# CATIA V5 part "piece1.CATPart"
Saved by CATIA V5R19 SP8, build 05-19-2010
Part number: piece1
Bounding box of the stored display mesh (mm): x -20 to 20, y -85.522 to 100.479, z -20 to 67.521
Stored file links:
  U:\554\piece1.CATPart
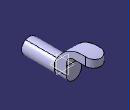
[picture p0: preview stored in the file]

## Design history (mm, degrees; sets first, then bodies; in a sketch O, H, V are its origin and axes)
Body1 (main body)
  Sketch1 on yz-plane, origin (0, 0, 0), H (0, 1, 0), V (0, 0, 1)
    point P1 (-85.5219, 0)
    line L1 (-85.5219, 0) -> (0, 0)
    line L2 (0, 0) -> (0, 20)
    line L3 (0, 20) -> (-85.5219, 20)
    line L4 (-85.5219, 20) -> (-85.5219, 0)
    point P3 (0, 20)
    length L4 = 20
    coincidence: P1 H, P3 V
    horizontal: L1 H, L3 H
    vertical: L2 V, L4 V
  Shaft1: profile Sketch1, axis Sketch1.L1, angle 360
  Sketch2 on yz-plane, origin (0, 0, 0), H (0, 1, 0), V (0, 0, 1)
    spline S1 through (0, 14.9789) (40.6517, 60.2998) (100.4787, 64.5247)
    point P1 (0, -22.9588)
    line L1 (0, -22.9588) -> (30.4581, -22.9588)
    line L2 (30.4581, -22.9588) -> (30.4581, 20.7401)
    line L3 (100.4787, 64.5247) -> (100.4787, 46.089)
    line L4 (100.4787, 46.089) -> (48.3218, 46.089)
    point P6 (100.4787, 64.5247)
    connectcurve C1
    line L5 (0, 14.9789) -> (0, -22.9588)
    point P7 (0, 14.9789)
    point P8 (0, 14.9789)
    point P9 (100.4787, 64.5247)
    coincidence: P8 V, P1 V, P9 P6, P8 P7
    horizontal: L1 H, L4 H
    vertical: L2 V, L3 V, L5 V
  Pad1: profile Sketch2, direction (1, 0, 0), length 20, mirrored extent
  Sketch3 on face of Pad1 from Sketch2.L2, origin (0, 30.4581, 0), H (-1, 0, 0), V (0, 0, 1)
    arc A1 centre (0, 0) radius 20 from (-20, 0) to (20, 0) ccw
    point P1 (20, 0)
    line L1 (20, 0) -> (51.8214, 0)
    line L2 (51.8214, 0) -> (51.8214, -50.6716)
    line L3 (51.8214, -50.6716) -> (-51.8214, -50.6716)
    line L4 (-51.8214, -50.6716) -> (-51.8214, 0)
    point P5 (-51.8214, 0)
    line L5 (-51.8214, 0) -> (-20, 0)
    point P6 (-20, 0)
    point P7 (-20, 0)
    point P8 (20, 0)
    reference projected circle E1 centre (0, 0) radius 20 from edge [face of Shaft1 from Sketch1.L4 | face of Shaft1 from Sketch1.L3]
    coincidence: P1 A1, P1 H, P5 H, P6 A1, L1 P8, L5 P7, A1 E1, P1 P8, P6 P7
    horizontal: L1 H, L3 H, L5 H
    vertical: L2 V, L4 V
    symmetry: L4 L2 V
  Pocket1: profile Sketch3, direction (0, -1, 0), through (limit type 3)
  Sketch4 on face of Pad1 from Sketch2.L4, origin (0, 0, 46.089), H (1, 0, 0), V (0, -1, 0)
    arc A1 centre (0, -80.4787) radius 20 from (-20, -80.4787) to (20, -80.4787) ccw
    point P1 (0, -80.4787)
    axis line L1 (0, 0) -> (0, -128.8511)
    reference projected line E1 (-20, -100.4787) -> (20, -100.4787) from edge [face of Pad1 from Sketch2.L3 | face of Pad1 from Sketch2.L4]
    line L2 (-20, -80.4787) -> (-106.2968, -80.4787)
    line L3 (-106.2968, -80.4787) -> (-106.2968, -135.4459)
    line L4 (-106.2968, -135.4459) -> (106.2968, -135.4459)
    line L5 (106.2968, -135.4459) -> (106.2968, -80.4787)
    point P7 (106.2968, -80.4787)
    line L6 (106.2968, -80.4787) -> (20, -80.4787)
    point P8 (20, -80.4787)
    point P9 (20, -80.4787)
    reference projected line E2 (-20, -100.4787) -> (20, -100.4787) from edge [face of Pad1 from Sketch2.L3 | face of Pad1 from Sketch2.L4]
    radius A1 = 20
    distance P1 E1 = 20
    distance L6 E2 = 20
    vertical: L1 V, L3 V, L5 V
    coincidence: P1 L1, P7 L2, P8 A1, L6 P9, P8 P9
    horizontal: L2 H, L4 H, L6 H
    symmetry: L5 L3 V
  Pocket2: profile Sketch4, direction (0, 0, 1), through (limit type 3)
